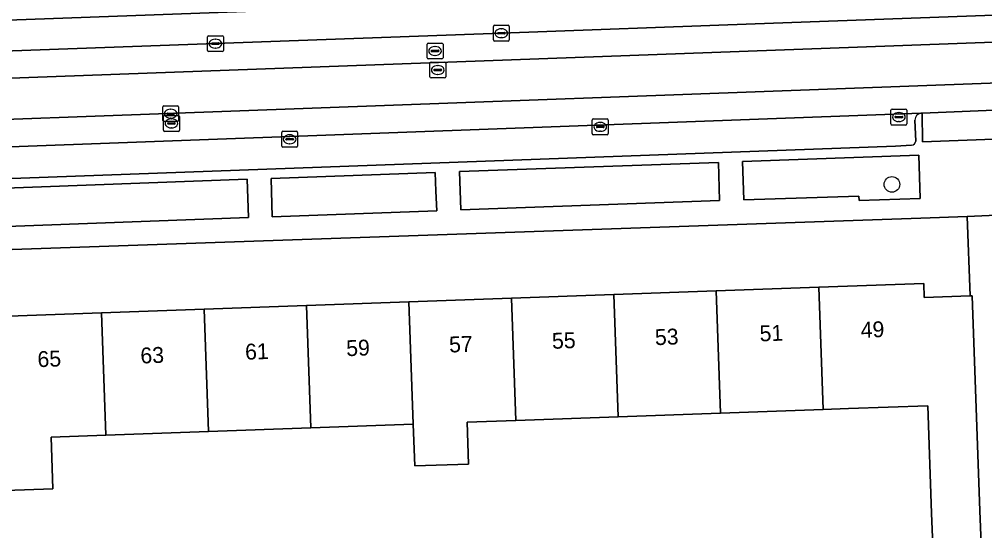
# Model space of a CAD drawing. Extents: x 160554 to 161248, y 385329 to 386506.
# Drawn here: x 160749.8 to 160810.5, y 386122.8 to 386154.9 of the extents above; entities that cross this region are included whole.
import ezdxf

# ---------------------------------------------------------------- set-up
doc = ezdxf.new("R2010")
doc.units = 0
for name, color, linetype in [('IMGEO_Boom', 7, 'Continuous'), ('IMGEO_Erf', 7, 'Continuous'), ('IMGEO_Groenvoorziening', 7, 'Continuous'), ('IMGEO_Kolk', 7, 'Continuous'), ('IMGEO_Pand', 7, 'Continuous'), ('IMGEO_Pand_nummerreeks', 7, 'Continuous'), ('IMGEO_Parkeervlak_open', 7, 'Continuous'), ('IMGEO_Rijbaan_lokaal_gesloten', 7, 'Continuous'), ('IMGEO_Rijbaan_lokaal_open', 7, 'Continuous'), ('IMGEO_Rioolput', 7, 'Continuous'), ('IMGEO_Voetpad_open', 7, 'Continuous')]:
    doc.layers.add(name, color=color, linetype=linetype)

msp = doc.modelspace()

# ---------------------------------------------------------------- linework, layer by layer
at = {"layer": 'IMGEO_Boom'}
msp.add_circle((160804.664, 386144.545), 0.489, dxfattribs=at)
at = {"layer": 'IMGEO_Erf'}
msp.add_lwpolyline([(160809.404, 386142.522), (160806.477, 386142.421), (160735.299, 386139.972), (160735.443, 386135.774), (160742.047, 386136.009), (160748.493, 386136.239), (160754.939, 386136.469), (160761.385, 386136.699), (160767.831, 386136.929), (160774.276, 386137.158), (160780.722, 386137.388), (160787.168, 386137.618), (160793.614, 386137.848), (160800.06, 386138.078), (160806.664, 386138.313), (160806.695, 386137.434), (160809.588, 386137.538)], close=True, dxfattribs=at)
msp.add_lwpolyline([(160807.434, 386117.213), (160807.156, 386123.872), (160806.915, 386130.616), (160801.943, 386130.439), (160800.335, 386130.382), (160793.889, 386130.152), (160787.443, 386129.923), (160780.997, 386129.693), (160777.939, 386129.584), (160778.033, 386126.952), (160774.645, 386126.831), (160774.551, 386129.463), (160768.106, 386129.233), (160761.66, 386129.004), (160755.214, 386128.774), (160751.763, 386128.651), (160751.879, 386125.398), (160748.884, 386125.291)], dxfattribs=at)
at = {"layer": 'IMGEO_Groenvoorziening'}
msp.add_lwpolyline([(160726.584, 386154.051), (160789.885, 386156.386), (160804.496, 386156.913), (160804.459, 386158.413)], dxfattribs=at)
for points in [[(160795.255, 386145.994), (160795.343, 386143.572), (160802.583, 386143.808), (160802.597, 386143.526), (160806.443, 386143.662), (160806.349, 386146.392)], [(160777.457, 386145.358), (160777.538, 386142.948), (160793.826, 386143.523), (160793.753, 386145.932)], [(160775.923, 386145.295), (160765.61, 386144.925), (160765.67, 386142.51), (160776.027, 386142.887), (160775.977, 386144.118)], [(160764.098, 386144.882), (160747.766, 386144.265), (160747.847, 386141.862), (160764.177, 386142.466)]]:
    msp.add_lwpolyline(points, close=True, dxfattribs=at)
at = {"layer": 'IMGEO_Kolk'}
for p, q in [((160779.589, 386153.629), (160779.589, 386154.481)), ((160779.664, 386154.555), (160780.516, 386154.555)), ((160780.077, 386154.335), (160780.102, 386154.335)), ((160780.59, 386154.481), (160780.59, 386153.629)), ((160761.599, 386152.972), (160761.599, 386153.824)), ((160761.674, 386153.898), (160762.526, 386153.898)), ((160762.087, 386153.678), (160762.112, 386153.678)), ((160762.6, 386153.824), (160762.6, 386152.972)), ((160780.516, 386153.555), (160779.664, 386153.555)), ((160779.848, 386154.049), (160779.848, 386154.061)), ((160780.286, 386154.012), (160779.888, 386154.012)), ((160779.891, 386154.098), (160780.289, 386154.098)), ((160780.1, 386153.775), (160780.075, 386153.775)), ((160780.332, 386154.061), (160780.332, 386154.049)), ((160762.526, 386152.898), (160761.674, 386152.898)), ((160761.858, 386153.392), (160761.858, 386153.404)), ((160762.296, 386153.355), (160761.898, 386153.355)), ((160761.901, 386153.441), (160762.299, 386153.441)), ((160762.11, 386153.118), (160762.085, 386153.118)), ((160762.342, 386153.404), (160762.342, 386153.392)), ((160804.675, 386149.28), (160805.527, 386149.28)), ((160785.886, 386148.663), (160786.738, 386148.663)), ((160804.6, 386148.354), (160804.6, 386149.206)), ((160804.859, 386148.774), (160804.859, 386148.786)), ((160805.297, 386148.737), (160804.899, 386148.737)), ((160804.902, 386148.823), (160805.3, 386148.823)), ((160805.088, 386149.06), (160805.113, 386149.06)), ((160805.343, 386148.786), (160805.343, 386148.774)), ((160805.601, 386149.206), (160805.601, 386148.354)), ((160785.811, 386147.737), (160785.811, 386148.589)), ((160786.07, 386148.157), (160786.07, 386148.169)), ((160786.508, 386148.12), (160786.11, 386148.12)), ((160786.113, 386148.206), (160786.511, 386148.206)), ((160786.299, 386148.443), (160786.324, 386148.443)), ((160786.554, 386148.169), (160786.554, 386148.157)), ((160786.812, 386148.589), (160786.812, 386147.737)), ((160805.527, 386148.28), (160804.675, 386148.28)), ((160805.111, 386148.5), (160805.086, 386148.5)), ((160766.271, 386146.958), (160766.271, 386147.81)), ((160766.346, 386147.884), (160767.198, 386147.884)), ((160766.573, 386147.427), (160766.971, 386147.427)), ((160766.759, 386147.664), (160766.784, 386147.664)), ((160767.272, 386147.81), (160767.272, 386146.958)), ((160786.738, 386147.663), (160785.886, 386147.663)), ((160786.322, 386147.883), (160786.297, 386147.883)), ((160767.198, 386146.884), (160766.346, 386146.884)), ((160766.53, 386147.378), (160766.53, 386147.39)), ((160766.968, 386147.341), (160766.57, 386147.341)), ((160766.782, 386147.104), (160766.757, 386147.104)), ((160767.014, 386147.39), (160767.014, 386147.378))]:
    msp.add_line(p, q, dxfattribs=at)
for points in [[(160779.589, 386153.629), (160779.589, 386154.481)], [(160779.664, 386154.555), (160780.516, 386154.555)], [(160780.59, 386154.481), (160780.59, 386153.629)], [(160761.599, 386152.972), (160761.599, 386153.824)], [(160761.674, 386153.898), (160762.526, 386153.898)], [(160762.6, 386153.824), (160762.6, 386152.972)], [(160780.516, 386153.555), (160779.664, 386153.555)], [(160762.526, 386152.898), (160761.674, 386152.898)], [(160804.675, 386149.28), (160805.527, 386149.28)], [(160785.886, 386148.663), (160786.738, 386148.663)], [(160804.6, 386148.354), (160804.6, 386149.206)], [(160805.601, 386149.206), (160805.601, 386148.354)], [(160785.811, 386147.737), (160785.811, 386148.589)], [(160786.812, 386148.589), (160786.812, 386147.737)], [(160805.527, 386148.28), (160804.675, 386148.28)], [(160766.271, 386146.958), (160766.271, 386147.81)], [(160766.346, 386147.884), (160767.198, 386147.884)], [(160767.272, 386147.81), (160767.272, 386146.958)], [(160786.738, 386147.663), (160785.886, 386147.663)], [(160767.198, 386146.884), (160766.346, 386146.884)]]:
    msp.add_lwpolyline(points, dxfattribs=at)
for centre, radius, start, end in [((160779.666, 386154.479), 0.0765, 91.55205, 178.44795), ((160779.666, 386154.479), 0.0765, 91.55205, 178.44795), ((160780.514, 386154.479), 0.0765, 1.55205, 88.44795), ((160780.514, 386154.479), 0.0765, 1.55205, 88.44795), ((160761.676, 386153.822), 0.0765, 91.55205, 178.44795), ((160761.676, 386153.822), 0.0765, 91.55205, 178.44795), ((160762.524, 386153.822), 0.0765, 1.55205, 88.44795), ((160762.524, 386153.822), 0.0765, 1.55205, 88.44795), ((160779.666, 386153.631), 0.0765, 181.55205, 268.44795), ((160779.666, 386153.631), 0.0765, 181.55205, 268.44795), ((160779.888, 386154.058), 0.0403, 85.87752, 175.75265), ((160779.885, 386154.048), 0.0366, 178.93798, 274.71019), ((160780.289, 386154.055), 0.043, 264.86636, 352.45326), ((160780.293, 386154.06), 0.0386, 1.73085, 96.63898), ((160780.514, 386153.631), 0.0765, 271.55205, 358.44795), ((160780.514, 386153.631), 0.0765, 271.55205, 358.44795), ((160761.676, 386152.974), 0.0765, 181.55205, 268.44795), ((160761.676, 386152.974), 0.0765, 181.55205, 268.44795), ((160761.898, 386153.401), 0.0403, 85.87752, 175.75265), ((160761.895, 386153.391), 0.0366, 178.93798, 274.71019), ((160762.299, 386153.398), 0.043, 264.86636, 352.45326), ((160762.303, 386153.403), 0.0386, 1.73085, 96.63898), ((160762.524, 386152.974), 0.0765, 271.55205, 358.44795), ((160762.524, 386152.974), 0.0765, 271.55205, 358.44795), ((160804.677, 386149.204), 0.0765, 91.55205, 178.44795), ((160804.677, 386149.204), 0.0765, 91.55205, 178.44795), ((160805.525, 386149.204), 0.0765, 1.55205, 88.44795), ((160805.525, 386149.204), 0.0765, 1.55205, 88.44795), ((160785.888, 386148.587), 0.0765, 91.55205, 178.44795), ((160785.888, 386148.587), 0.0765, 91.55205, 178.44795), ((160786.736, 386148.587), 0.0765, 1.55205, 88.44795), ((160786.736, 386148.587), 0.0765, 1.55205, 88.44795), ((160804.899, 386148.783), 0.0403, 85.87752, 175.75265), ((160804.896, 386148.773), 0.0366, 178.93798, 274.71019), ((160805.3, 386148.78), 0.043, 264.86636, 352.45326), ((160805.304, 386148.785), 0.0386, 1.73085, 96.63898), ((160786.11, 386148.166), 0.0403, 85.87752, 175.75265), ((160786.107, 386148.156), 0.0366, 178.93798, 274.71019), ((160786.511, 386148.163), 0.043, 264.86636, 352.45326), ((160786.515, 386148.168), 0.0386, 1.73085, 96.63898), ((160804.677, 386148.356), 0.0765, 181.55205, 268.44795), ((160804.677, 386148.356), 0.0765, 181.55205, 268.44795), ((160805.525, 386148.356), 0.0765, 271.55205, 358.44795), ((160805.525, 386148.356), 0.0765, 271.55205, 358.44795), ((160766.348, 386147.808), 0.0765, 91.55205, 178.44795), ((160766.348, 386147.808), 0.0765, 91.55205, 178.44795), ((160766.57, 386147.387), 0.0403, 85.87752, 175.75265), ((160766.975, 386147.389), 0.0386, 1.73085, 96.63898), ((160767.196, 386147.808), 0.0765, 1.55205, 88.44795), ((160767.196, 386147.808), 0.0765, 1.55205, 88.44795), ((160785.888, 386147.739), 0.0765, 181.55205, 268.44795), ((160785.888, 386147.739), 0.0765, 181.55205, 268.44795), ((160786.736, 386147.739), 0.0765, 271.55205, 358.44795), ((160786.736, 386147.739), 0.0765, 271.55205, 358.44795), ((160766.348, 386146.96), 0.0765, 181.55205, 268.44795), ((160766.348, 386146.96), 0.0765, 181.55205, 268.44795), ((160766.567, 386147.377), 0.0366, 178.93798, 274.71019), ((160766.971, 386147.384), 0.043, 264.86636, 352.45326), ((160767.196, 386146.96), 0.0765, 271.55205, 358.44795), ((160767.196, 386146.96), 0.0765, 271.55205, 358.44795)]:
    msp.add_arc(centre, radius, start, end, dxfattribs=at)
for centre, major_axis, ratio, start_param, end_param in [((160780.076, 386154.055), (-0.387, 0.002), 0.722429, 4.712389, 7.853982), ((160780.101, 386154.055), (-0.39, 0.002), 0.717154, 1.570796, 4.712389), ((160762.086, 386153.398), (-0.387, 0.002), 0.722429, 4.712389, 7.853982), ((160762.111, 386153.398), (-0.39, 0.002), 0.717154, 1.570796, 4.712389), ((160805.087, 386148.78), (-0.387, 0.002), 0.722429, 4.712389, 7.853982), ((160805.112, 386148.78), (-0.39, 0.002), 0.717154, 1.570796, 4.712389), ((160786.298, 386148.163), (-0.387, 0.002), 0.722429, 4.712389, 7.853982), ((160786.323, 386148.163), (-0.39, 0.002), 0.717154, 1.570796, 4.712389), ((160766.758, 386147.384), (-0.387, 0.002), 0.722429, 4.712389, 7.853982), ((160766.783, 386147.384), (-0.39, 0.002), 0.717154, 1.570796, 4.712389)]:
    msp.add_ellipse(centre, major_axis=major_axis, ratio=ratio, start_param=start_param, end_param=end_param, dxfattribs=at)
at = {"layer": 'IMGEO_Pand'}
for points in [[(160800.335, 386130.382), (160801.943, 386130.439), (160806.915, 386130.616), (160807.156, 386123.872), (160807.434, 386117.213), (160810.477, 386117.34), (160810.199, 386123.999), (160809.715, 386137.542), (160809.588, 386137.538), (160806.695, 386137.434), (160806.664, 386138.313), (160800.06, 386138.078)], [(160793.614, 386137.848), (160787.168, 386137.618), (160787.443, 386129.923), (160793.889, 386130.152)], [(160793.889, 386130.152), (160800.335, 386130.382), (160800.06, 386138.078), (160793.614, 386137.848)], [(160774.276, 386137.158), (160767.831, 386136.929), (160768.106, 386129.233), (160774.551, 386129.463)], [(160774.551, 386129.463), (160774.645, 386126.831), (160778.033, 386126.952), (160777.939, 386129.584), (160780.997, 386129.693), (160780.722, 386137.388), (160774.276, 386137.158)], [(160780.997, 386129.693), (160787.443, 386129.923), (160787.168, 386137.618), (160780.722, 386137.388)], [(160755.214, 386128.774), (160761.66, 386129.004), (160761.385, 386136.699), (160754.939, 386136.469)], [(160761.66, 386129.004), (160768.106, 386129.233), (160767.831, 386136.929), (160761.385, 386136.699)], [(160755.214, 386128.774), (160754.939, 386136.469), (160748.493, 386136.239), (160748.768, 386128.544), (160748.884, 386125.291), (160751.879, 386125.398), (160751.763, 386128.651)]]:
    msp.add_lwpolyline(points, close=True, dxfattribs=at)
at = {"layer": 'IMGEO_Parkeervlak_open'}
for points in [[(160806.476, 386149.019), (160734.993, 386146.392), (160735.066, 386144.651)], [(160806.161, 386147.261), (160806.113, 386148.594)], [(160735.35, 386144.409), (160736.079, 386144.436), (160804.896, 386146.94), (160805.905, 386147.009)]]:
    msp.add_lwpolyline(points, dxfattribs=at)
for centre, radius, start, end in [((160806.534, 386148.602), 0.421, 97.96475, 181.0328), ((160805.88, 386147.291), 0.283, 275.13173, 353.96599)]:
    msp.add_arc(centre, radius, start, end, dxfattribs=at)
at = {"layer": 'IMGEO_Rijbaan_lokaal_gesloten'}
msp.add_lwpolyline([(160834.064, 386154.328), (160833.979, 386156.036), (160832.121, 386155.974), (160826.115, 386155.745), (160796.064, 386154.65), (160780.09, 386154.054), (160762.105, 386153.4), (160744.095, 386152.749), (160725.861, 386152.062), (160714.387, 386151.668), (160713.317, 386151.63), (160703.238, 386151.261), (160702.292, 386151.238), (160690.182, 386150.794), (160689.63, 386150.777), (160689.851, 386149.047), (160748.65, 386151.198), (160802.504, 386153.169), (160827.576, 386154.097)], close=True, dxfattribs=at)
for points in [[(160806.476, 386149.019), (160806.56, 386149.022), (160816.633, 386149.435), (160818.726, 386149.381), (160832.098, 386149.898), (160834.283, 386150.031), (160834.176, 386151.782), (160735.181, 386148.132), (160703.104, 386146.996)], [(160703.22, 386145.271), (160729.151, 386146.198), (160734.513, 386146.374), (160734.993, 386146.392), (160806.476, 386149.019)]]:
    msp.add_lwpolyline(points, dxfattribs=at)
at = {"layer": 'IMGEO_Rijbaan_lokaal_open'}
for points in [[(160834.176, 386151.782), (160834.064, 386154.328), (160827.576, 386154.097), (160802.504, 386153.169), (160748.65, 386151.198), (160689.851, 386149.047), (160690.275, 386145.788), (160694.256, 386146.327), (160697.634, 386146.691)], [(160703.104, 386146.996), (160735.181, 386148.132), (160834.176, 386151.782)], [(160813.563, 386142.706), (160809.404, 386142.522), (160809.588, 386137.538), (160809.715, 386137.542), (160810.199, 386123.999), (160810.477, 386117.34), (160807.434, 386117.213), (160806.912, 386117.203), (160800.973, 386117.086), (160798.286, 386116.987), (160736.193, 386114.703)]]:
    msp.add_lwpolyline(points, dxfattribs=at)
at = {"layer": 'IMGEO_Rioolput'}
for p, q in [((160775.419, 386152.51), (160775.419, 386153.362)), ((160775.494, 386153.436), (160776.346, 386153.436)), ((160775.678, 386152.93), (160775.678, 386152.942)), ((160776.116, 386152.893), (160775.718, 386152.893)), ((160775.721, 386152.979), (160776.119, 386152.979)), ((160775.907, 386153.216), (160775.932, 386153.216)), ((160776.162, 386152.942), (160776.162, 386152.93)), ((160776.42, 386153.362), (160776.42, 386152.51)), ((160776.346, 386152.436), (160775.494, 386152.436)), ((160775.93, 386152.656), (160775.905, 386152.656)), ((160775.592, 386151.315), (160775.592, 386152.167)), ((160775.667, 386152.241), (160776.519, 386152.241)), ((160775.851, 386151.735), (160775.851, 386151.747)), ((160776.289, 386151.698), (160775.891, 386151.698)), ((160775.894, 386151.784), (160776.292, 386151.784)), ((160776.08, 386152.021), (160776.105, 386152.021)), ((160776.335, 386151.747), (160776.335, 386151.735)), ((160776.593, 386152.167), (160776.593, 386151.315)), ((160776.519, 386151.241), (160775.667, 386151.241)), ((160776.103, 386151.461), (160776.078, 386151.461)), ((160758.784, 386148.565), (160758.784, 386149.417)), ((160758.859, 386149.491), (160759.711, 386149.491)), ((160759.272, 386149.271), (160759.297, 386149.271)), ((160759.785, 386149.417), (160759.785, 386148.565)), ((160758.833, 386147.953), (160758.833, 386148.805)), ((160758.908, 386148.879), (160759.76, 386148.879)), ((160759.043, 386148.985), (160759.043, 386148.997)), ((160759.481, 386148.948), (160759.083, 386148.948)), ((160759.086, 386149.034), (160759.484, 386149.034)), ((160759.295, 386148.711), (160759.27, 386148.711)), ((160759.321, 386148.659), (160759.346, 386148.659)), ((160759.527, 386148.997), (160759.527, 386148.985)), ((160759.834, 386148.805), (160759.834, 386147.953)), ((160759.711, 386148.491), (160758.859, 386148.491)), ((160759.092, 386148.373), (160759.092, 386148.385)), ((160759.53, 386148.336), (160759.132, 386148.336)), ((160759.135, 386148.422), (160759.533, 386148.422)), ((160759.344, 386148.099), (160759.319, 386148.099)), ((160759.576, 386148.385), (160759.576, 386148.373)), ((160759.76, 386147.879), (160758.908, 386147.879))]:
    msp.add_line(p, q, dxfattribs=at)
for points in [[(160775.419, 386152.51), (160775.419, 386153.362)], [(160775.494, 386153.436), (160776.346, 386153.436)], [(160776.42, 386153.362), (160776.42, 386152.51)], [(160776.346, 386152.436), (160775.494, 386152.436)], [(160775.592, 386151.315), (160775.592, 386152.167)], [(160775.667, 386152.241), (160776.519, 386152.241)], [(160776.593, 386152.167), (160776.593, 386151.315)], [(160776.519, 386151.241), (160775.667, 386151.241)], [(160758.784, 386148.565), (160758.784, 386149.417)], [(160758.859, 386149.491), (160759.711, 386149.491)], [(160759.785, 386149.417), (160759.785, 386148.565)], [(160758.833, 386147.953), (160758.833, 386148.805)], [(160758.908, 386148.879), (160759.76, 386148.879)], [(160759.834, 386148.805), (160759.834, 386147.953)], [(160759.711, 386148.491), (160758.859, 386148.491)], [(160759.76, 386147.879), (160758.908, 386147.879)]]:
    msp.add_lwpolyline(points, dxfattribs=at)
for centre, radius, start, end in [((160775.496, 386153.36), 0.0765, 91.55205, 178.44795), ((160775.496, 386153.36), 0.0765, 91.55205, 178.44795), ((160775.718, 386152.939), 0.0403, 85.87752, 175.75265), ((160775.715, 386152.929), 0.0366, 178.93798, 274.71019), ((160776.119, 386152.936), 0.043, 264.86636, 352.45326), ((160776.123, 386152.941), 0.0386, 1.73085, 96.63898), ((160776.344, 386153.36), 0.0765, 1.55205, 88.44795), ((160776.344, 386153.36), 0.0765, 1.55205, 88.44795), ((160775.496, 386152.512), 0.0765, 181.55205, 268.44795), ((160775.496, 386152.512), 0.0765, 181.55205, 268.44795), ((160776.344, 386152.512), 0.0765, 271.55205, 358.44795), ((160776.344, 386152.512), 0.0765, 271.55205, 358.44795), ((160775.669, 386152.165), 0.0765, 91.55205, 178.44795), ((160775.669, 386152.165), 0.0765, 91.55205, 178.44795), ((160775.891, 386151.744), 0.0403, 85.87752, 175.75265), ((160775.888, 386151.734), 0.0366, 178.93798, 274.71019), ((160776.292, 386151.741), 0.043, 264.86636, 352.45326), ((160776.296, 386151.746), 0.0386, 1.73085, 96.63898), ((160776.517, 386152.165), 0.0765, 1.55205, 88.44795), ((160776.517, 386152.165), 0.0765, 1.55205, 88.44795), ((160775.669, 386151.317), 0.0765, 181.55205, 268.44795), ((160775.669, 386151.317), 0.0765, 181.55205, 268.44795), ((160776.517, 386151.317), 0.0765, 271.55205, 358.44795), ((160776.517, 386151.317), 0.0765, 271.55205, 358.44795), ((160758.861, 386149.415), 0.0765, 91.55205, 178.44795), ((160758.861, 386149.415), 0.0765, 91.55205, 178.44795), ((160759.709, 386149.415), 0.0765, 1.55205, 88.44795), ((160759.709, 386149.415), 0.0765, 1.55205, 88.44795), ((160758.91, 386148.803), 0.0765, 91.55205, 178.44795), ((160758.91, 386148.803), 0.0765, 91.55205, 178.44795), ((160759.083, 386148.994), 0.0403, 85.87752, 175.75265), ((160759.08, 386148.984), 0.0366, 178.93798, 274.71019), ((160759.484, 386148.991), 0.043, 264.86636, 352.45326), ((160759.488, 386148.996), 0.0386, 1.73085, 96.63898), ((160759.758, 386148.803), 0.0765, 1.55205, 88.44795), ((160759.758, 386148.803), 0.0765, 1.55205, 88.44795), ((160758.861, 386148.567), 0.0765, 181.55205, 268.44795), ((160758.861, 386148.567), 0.0765, 181.55205, 268.44795), ((160759.132, 386148.382), 0.0403, 85.87752, 175.75265), ((160759.129, 386148.372), 0.0366, 178.93798, 274.71019), ((160759.533, 386148.379), 0.043, 264.86636, 352.45326), ((160759.537, 386148.384), 0.0386, 1.73085, 96.63898), ((160759.709, 386148.567), 0.0765, 271.55205, 358.44795), ((160759.709, 386148.567), 0.0765, 271.55205, 358.44795), ((160758.91, 386147.955), 0.0765, 181.55205, 268.44795), ((160758.91, 386147.955), 0.0765, 181.55205, 268.44795), ((160759.758, 386147.955), 0.0765, 271.55205, 358.44795), ((160759.758, 386147.955), 0.0765, 271.55205, 358.44795)]:
    msp.add_arc(centre, radius, start, end, dxfattribs=at)
for centre, major_axis, ratio, start_param, end_param in [((160775.906, 386152.936), (-0.387, 0.002), 0.722429, 4.712389, 7.853982), ((160775.931, 386152.936), (-0.39, 0.002), 0.717154, 1.570796, 4.712389), ((160776.079, 386151.741), (-0.387, 0.002), 0.722429, 4.712389, 7.853982), ((160776.104, 386151.741), (-0.39, 0.002), 0.717154, 1.570796, 4.712389), ((160759.271, 386148.991), (-0.387, 0.002), 0.722429, 4.712389, 7.853982), ((160759.296, 386148.991), (-0.39, 0.002), 0.717154, 1.570796, 4.712389), ((160759.32, 386148.379), (-0.387, 0.002), 0.722429, 4.712389, 7.853982), ((160759.345, 386148.379), (-0.39, 0.002), 0.717154, 1.570796, 4.712389)]:
    msp.add_ellipse(centre, major_axis=major_axis, ratio=ratio, start_param=start_param, end_param=end_param, dxfattribs=at)
at = {"layer": 'IMGEO_Voetpad_open'}
for points in [[(160842.227, 386158.315), (160814.477, 386157.284), (160814.421, 386158.783), (160804.459, 386158.413), (160804.496, 386156.913), (160789.885, 386156.386), (160726.584, 386154.051)], [(160684.806, 386150.623), (160687.151, 386150.698), (160689.63, 386150.777), (160690.182, 386150.794), (160702.292, 386151.238), (160703.238, 386151.261), (160703.178, 386152.451), (160713.268, 386152.822), (160713.317, 386151.63), (160714.387, 386151.668), (160714.329, 386152.859), (160725.829, 386153.271), (160725.861, 386152.062), (160744.095, 386152.749), (160762.105, 386153.4), (160780.09, 386154.054), (160796.064, 386154.65), (160826.115, 386155.745)], [(160836.823, 386150.146), (160835.242, 386150.074), (160834.283, 386150.031), (160832.098, 386149.898), (160818.726, 386149.381), (160816.633, 386149.435), (160816.703, 386147.608), (160806.58, 386147.213), (160806.56, 386149.022), (160806.476, 386149.019)], [(160806.113, 386148.594), (160806.161, 386147.261)], [(160805.905, 386147.009), (160804.896, 386146.94), (160736.079, 386144.436), (160735.35, 386144.409)], [(160705.637, 386139.495), (160711.136, 386139.11), (160716.402, 386139.302), (160728.843, 386139.754), (160730.46, 386139.808), (160733.73, 386139.919), (160733.794, 386139.921), (160733.95, 386139.926), (160735.299, 386139.972), (160806.477, 386142.421), (160809.404, 386142.522), (160813.563, 386142.706), (160816.862, 386142.826), (160820.805, 386142.97), (160824.702, 386143.111), (160835.543, 386143.506)]]:
    msp.add_lwpolyline(points, dxfattribs=at)
for points in [[(160816.633, 386149.435), (160806.56, 386149.022), (160806.58, 386147.213), (160816.703, 386147.608)], [(160795.255, 386145.994), (160806.349, 386146.392), (160806.443, 386143.662), (160802.597, 386143.526), (160802.583, 386143.808), (160795.343, 386143.572)], [(160777.457, 386145.358), (160793.753, 386145.932), (160793.826, 386143.523), (160777.538, 386142.948)], [(160765.61, 386144.925), (160775.923, 386145.295), (160775.977, 386144.118), (160776.027, 386142.887), (160765.67, 386142.51)], [(160747.766, 386144.265), (160764.098, 386144.882), (160764.177, 386142.466), (160747.847, 386141.862)]]:
    msp.add_lwpolyline(points, close=True, dxfattribs=at)
for centre, radius, start, end in [((160806.534, 386148.602), 0.421, 97.96475, 181.0328), ((160805.88, 386147.291), 0.283, 275.13173, 353.96599)]:
    msp.add_arc(centre, radius, start, end, dxfattribs=at)

# ---------------------------------------------------------------- texts
at = {"layer": 'IMGEO_Pand_nummerreeks'}
for s, rotation, p in [('49', 2.04171, (160802.718, 386134.89)), ('53', 2.03973, (160789.769, 386134.429)), ('51', 2.04171, (160796.356, 386134.664)), ('59', 2.04171, (160770.345, 386133.736)), ('57', 2.04171, (160776.819, 386133.967)), ('55', 2.04171, (160783.294, 386134.198)), ('65', 2.04171, (160750.921, 386133.044)), ('63', 2.04171, (160757.396, 386133.275)), ('61', 2.04171, (160763.983, 386133.51))]:
    msp.add_text(s, height=1, rotation=rotation, dxfattribs=at).set_placement(p)

doc.saveas('drawing.dxf')
